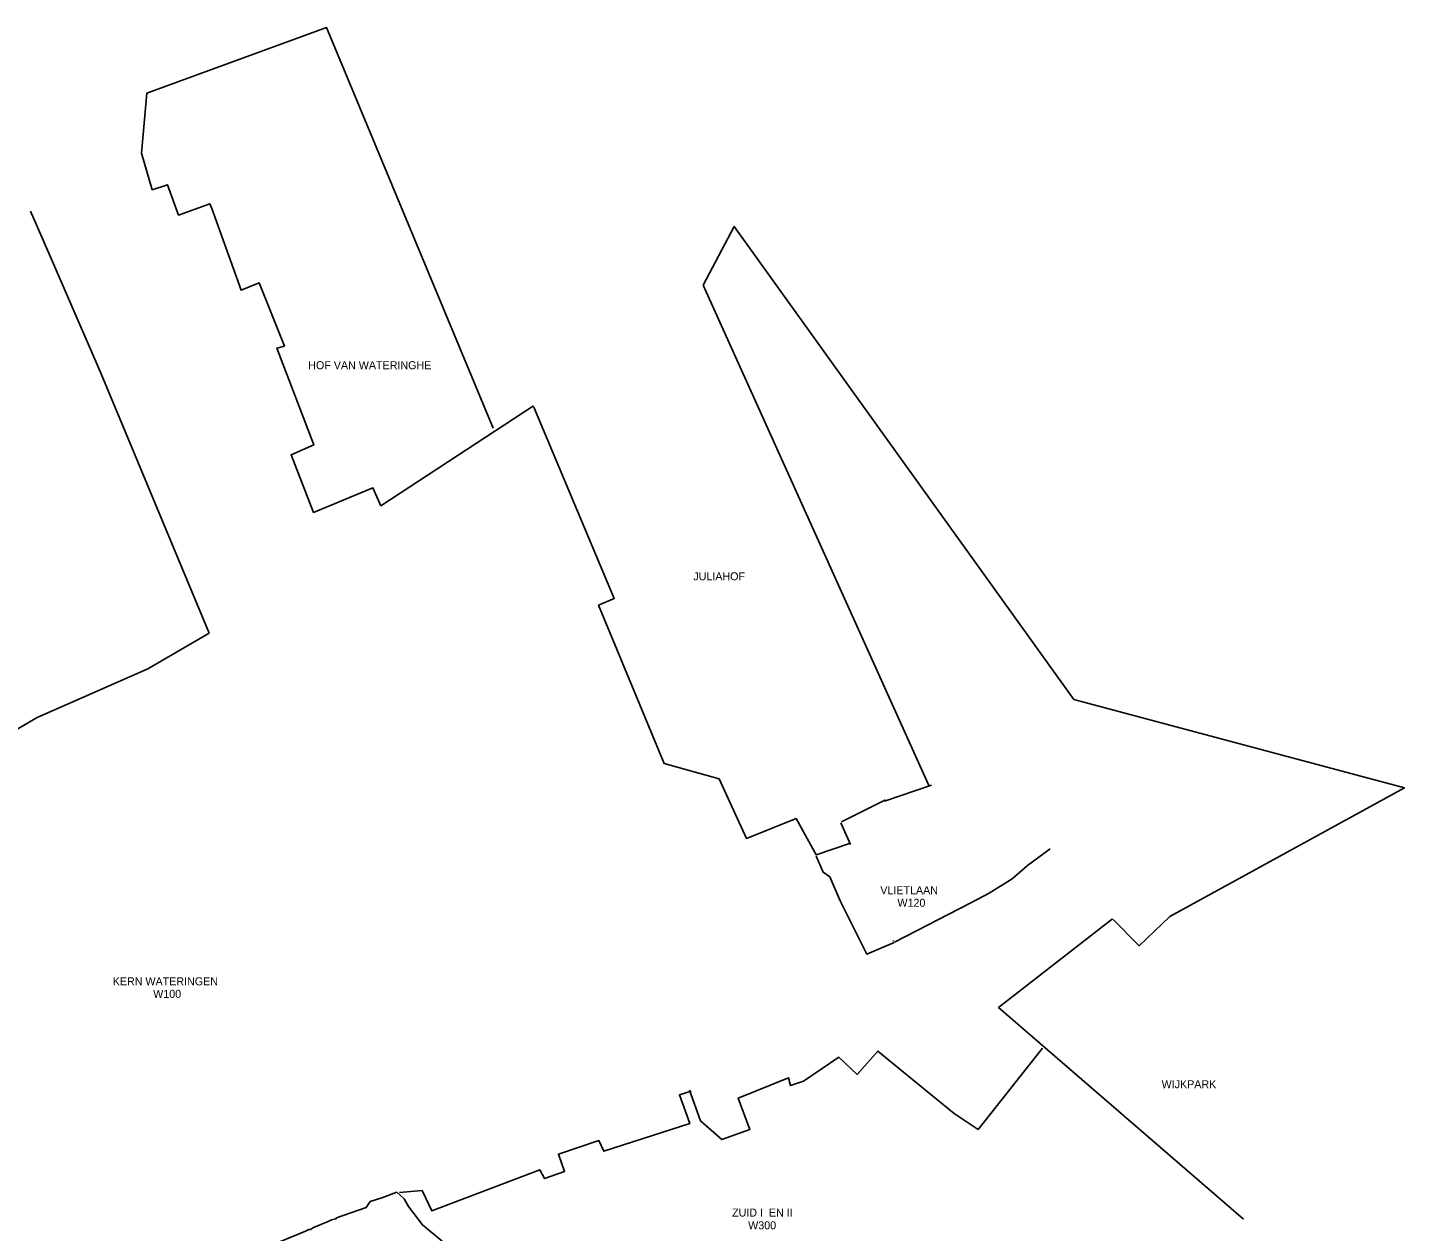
# Model space of a CAD drawing. Extents: x 69068 to 80855, y 440023 to 451362.
# Drawn here: x 78102 to 79650, y 448851 to 450206 of the extents above; entities that cross this region are included whole.
import ezdxf

# ---------------------------------------------------------------- set-up
doc = ezdxf.new("R2010")
doc.units = 0
for name, color, linetype in [('Bemalingsgebiedsgrens', 7, 'Continuous'), ('Bemalingsgebiedsnummer', 7, 'Continuous'), ('RIO_Leidingen', 7, 'Continuous')]:
    doc.layers.add(name, color=color, linetype=linetype)

msp = doc.modelspace()

# ---------------------------------------------------------------- linework, layer by layer
at = {"layer": 'Bemalingsgebiedsgrens'}
for p, q in [((79115.7, 449352.3), (78861.7, 449916)), ((79118.3, 449353.6), (79065.7, 449335.3)), ((79066.6, 449336.9), (79017.3, 449312.2)), ((79016.5, 449310.9), (79027.4, 449286.5)), ((79226.2, 449263.1), (79252, 449281.8)), ((79209.2, 449248.1), (79226.2, 449263.1)), ((79183.3, 449231.9), (79209.2, 449248.1)), ((79076.9, 449176.6), (79162.6, 449220.9)), ((79162.6, 449220.9), (79183.3, 449231.9)), ((79075.4, 449178.5), (79075.7, 449177.8))]:
    msp.add_line(p, q, dxfattribs=at)
for points in [[(78625.2, 449755.1), (78438.1, 450206.1), (78236, 450132.1), (78229.7, 450064.7)], [(78670.7, 449780.3), (78499.2, 449668), (78490.1, 449688.2), (78423.3, 449660.5), (78398, 449725.3), (78423.8, 449736.6), (78382.2, 449845.2), (78390.5, 449847.6), (78362.1, 449918.7), (78341.9, 449910.4), (78309.1, 450002.6), (78306.7, 450007.7), (78271.6, 449995.1), (78258.9, 450029.1), (78241.9, 450023.5), (78229.7, 450064.7)], [(78104.9, 449999.3), (78129.2, 449943.7), (78184.5, 449816.5), (78306, 449524.5)], [(78861.7, 449916), (78896.4, 449982.3), (79278.5, 449449.7), (79650.4, 449350.3), (79386.4, 449205.6)], [(79027.2, 449288), (78988.7, 449275), (78966.2, 449315.9), (78910.5, 449293.6), (78879.5, 449360.6), (78817.6, 449377.9), (78743.9, 449556), (78761.6, 449563.6), (78671.2, 449778.9), (78671.6, 449779.3)], [(78306, 449524.5), (78237, 449484.2), (78112.4, 449429.7), (78050, 449393.1), (77972.3, 449379), (77960.5, 449363.2), (77849.6, 449380.2), (77771, 449380.8), (77762.9, 449382.5)], [(78988.6, 449273.4), (78996.5, 449255.5), (79004.2, 449250.3), (79015.5, 449223.3), (79045.5, 449163.4), (79076.3, 449176.4)], [(79322.8, 449202.1), (79352, 449172.8), (79386.4, 449205.6)], [(79469.4, 448865), (79193.8, 449103.3), (79321.9, 449203)], [(78900.8, 449001.3), (78900.8, 449001.2), (78957.4, 449024.1), (78959.9, 449015.4), (78974.4, 449020.4), (79014.3, 449047.3), (79034.9, 449028), (79058.1, 449054.1), (79121.9, 449001.9), (79144, 448983.8), (79170.8, 448966), (79243.3, 449057.4)], [(78520.2, 448894.9), (78545.7, 448897.2), (78556.5, 448874.3), (78677.9, 448920.4), (78683.2, 448910.6), (78705.7, 448918.5), (78698.8, 448938.3), (78744.3, 448953.4), (78749.9, 448941.4), (78846.5, 448972.6), (78834.9, 449004.8), (78848.1, 449009.1)], [(78901.1, 449001), (78913.9, 448965.9), (78882.7, 448954.5), (78858.6, 448975.6), (78846.3, 449010.2)], [(78568.1, 448840.2), (78546, 448858.6), (78530, 448879.3), (78525.4, 448887.8), (78517.1, 448895.3), (78500.3, 448889), (78487.1, 448884.7), (78482.4, 448878.1), (78449.3, 448866.5), (78448.5, 448865.2), (78443.6, 448864.2), (78439.8, 448862.5), (78423.4, 448855.8), (78420.1, 448853.3), (78417.9, 448853.5), (78414.3, 448851.4), (78368.9, 448832.8)]]:
    msp.add_lwpolyline(points, dxfattribs=at)

# ---------------------------------------------------------------- texts
at = {"layer": 'Bemalingsgebiedsnummer'}
for s, p in [('W120', (79080.1, 449216.6)), ('W100', (78243, 449114.1)), ('W300', (78912.2, 448853.6))]:
    msp.add_text(s, height=9, dxfattribs=at).set_placement(p)
at = {"layer": 'RIO_Leidingen'}
for s, p in [('HOF VAN WATERINGHE', (78417.4, 449821.6)), ('JULIAHOF', (78850.5, 449584)), ('VLIETLAAN', (79060.8, 449230.7)), ('KERN WATERINGEN', (78197.5, 449128.2)), ('WIJKPARK', (79377.2, 449012.4)), ('ZUID I  EN II', (78894.1, 448867.9))]:
    msp.add_text(s, height=9, dxfattribs=at).set_placement(p)

doc.saveas('drawing.dxf')
